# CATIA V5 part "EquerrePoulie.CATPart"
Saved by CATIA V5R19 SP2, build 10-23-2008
Part number: EquerrePoulie
Bounding box of the stored display mesh (mm): x -10 to 10, y 0 to 40, z 0 to 60
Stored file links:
  D:\SCHOOL\FRANCE\BANC_POUTRE_EN_MOUSSE\EquerrePoulie.CATPart
  C:\Program Files\Dassault Systemes\B19\intel_a\reffiles\standard\MetricThickPitch.txt
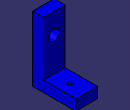
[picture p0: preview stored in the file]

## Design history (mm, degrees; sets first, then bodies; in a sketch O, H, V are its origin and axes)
AxisSystem1: origin (0, 0, 0), X (1, 0, 0), Y (0, 1, 0), Z (0, 0, 1)
Body1 (main body)
  Sketch1 on YZ plane of AxisSystem1, origin (0, 0, 0), H (0, 1, 0), V (0, 0, 1)
    point P1 (0, 60)
    line L1 (0, 60) -> (0, 0)
    line L2 (0, 0) -> (40, 0)
    line L3 (40, 0) -> (40, 10)
    line L4 (40, 10) -> (10, 10)
    line L5 (10, 10) -> (10, 60)
    line L6 (10, 60) -> (0, 60)
    length L6 = 10
    length L3 = 10
    length L2 = 40
    length L1 = 60
    coincidence: P1 V
    vertical: L1 V, L3 V, L5 V
    horizontal: L2 H, L4 H, L6 H
  Pad1: profile Sketch1, direction (1, 0, 0), length 10, opposite side length 10
  Sketch2 on face of Pad1 from Sketch1.L1, origin (-0.6083, 0, 43.0442), H (1, 0, 0), V (0, 0, 1)
    point P1 (0.6083, -2.0442)
    axis line L1 (0.6083, 27.4) -> (0.6083, -73.6539)
    reference intersected line E1 through (0.6083, 0) direction (0, 1) from YZ plane of AxisSystem1
    reference intersected line E2 through (0, -43.0442) direction (-1, 0) from XY plane of AxisSystem1
    distance E2 P1 = 41
    vertical: L1 V
    coincidence: L1 E1, L1 P1
  Hole1: placed by Sketch2, at (0, 0, 41) direction (0, 1, 0), diameter 10, through (limit type 6)
  Sketch3 on face of Pad1 from Sketch1.L2, origin (2.0625, 24.1251, 0), H (1, 0, 0), V (0, -1, 0)
    point P1 (-2.0625, -0.8749)
    axis line L1 (-2.0625, 45.5606) -> (-2.0625, -48.0425)
    reference intersected line E1 through (-2.0625, 0) direction (0, 1) from YZ plane of AxisSystem1
    reference intersected line E2 through (0, 24.1251) direction (1, 0) from ZX plane of AxisSystem1
    distance E2 P1 = 25
    vertical: L1 V
    coincidence: L1 E1, P1 L1
  Hole2: placed by Sketch3, at (0, 25, 0) direction (0, 0, 1), diameter 4.917, through (limit type 6)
